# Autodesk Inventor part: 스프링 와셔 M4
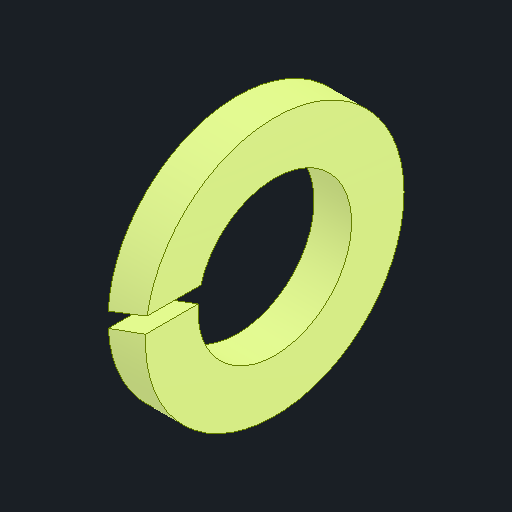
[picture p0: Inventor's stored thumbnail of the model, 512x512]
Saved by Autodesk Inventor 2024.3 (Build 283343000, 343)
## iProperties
Created: 2024-05
Part Number: 스프링 와셔 M4
Material: 강철, 연강
Description: 스프링 잠금 와셔
Document SubType Name: Modeling
Designer: MyPc
Density: 7.85 g/cm^3
Appearance: 기본값
Author: jhkim
Sending System: Autodesk Inventor 2025
Preprocessor: ST-DEVELOPER v20
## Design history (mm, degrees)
node "스프링 와셔 M41"
node "솔리드1"
body "Solid1"
